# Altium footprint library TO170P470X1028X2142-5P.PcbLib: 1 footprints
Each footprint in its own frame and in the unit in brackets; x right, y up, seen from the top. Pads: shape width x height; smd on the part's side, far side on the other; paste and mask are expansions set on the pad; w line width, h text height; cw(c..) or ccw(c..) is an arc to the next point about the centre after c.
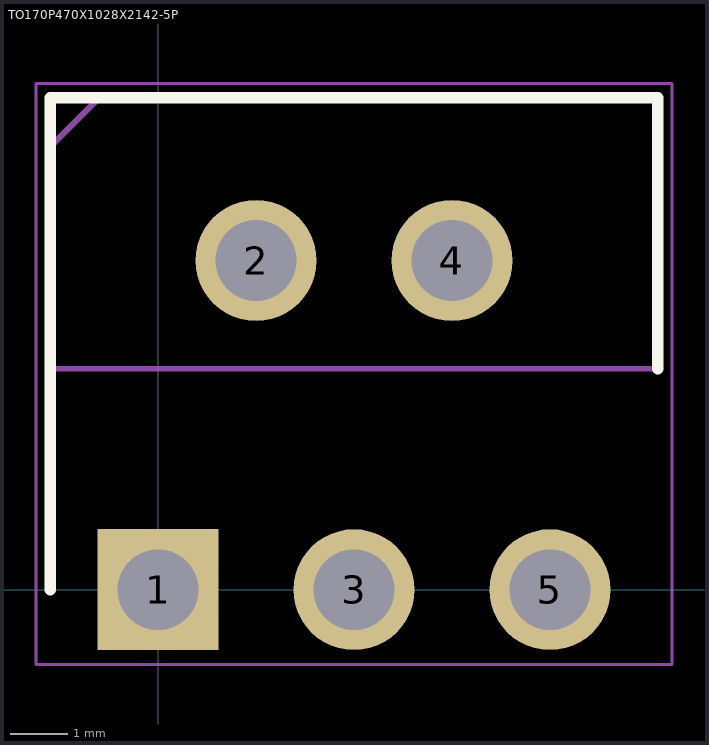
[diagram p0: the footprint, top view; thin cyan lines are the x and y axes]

## TO170P470X1028X2142-5P [mm]
pads (5):
  rect 2.1x2.1 / inner round 2.1 / far side rect 2.1x2.1 hole 1.4: 1(0,0)
  round 2.1 hole 1.4: 2(1.7,5.71) 3(3.4,0) 4(5.1,5.71) 5(6.8,0)
Top Overlay:
  lines w0.2: -1.87,0 -1.87,8.535 8.67,8.535 8.67,3.835
Mechanical 15:
  lines w0.1: -1.87,7.685 -1.02,8.535 ; -1.87,3.835 8.67,3.835 8.67,8.535 -1.87,8.535 -1.87,3.835
Mechanical 20:
  lines w0.05: -2.12,-1.3 8.92,-1.3 8.92,8.785 -2.12,8.785 -2.12,-1.3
